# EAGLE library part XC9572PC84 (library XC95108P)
CPLD
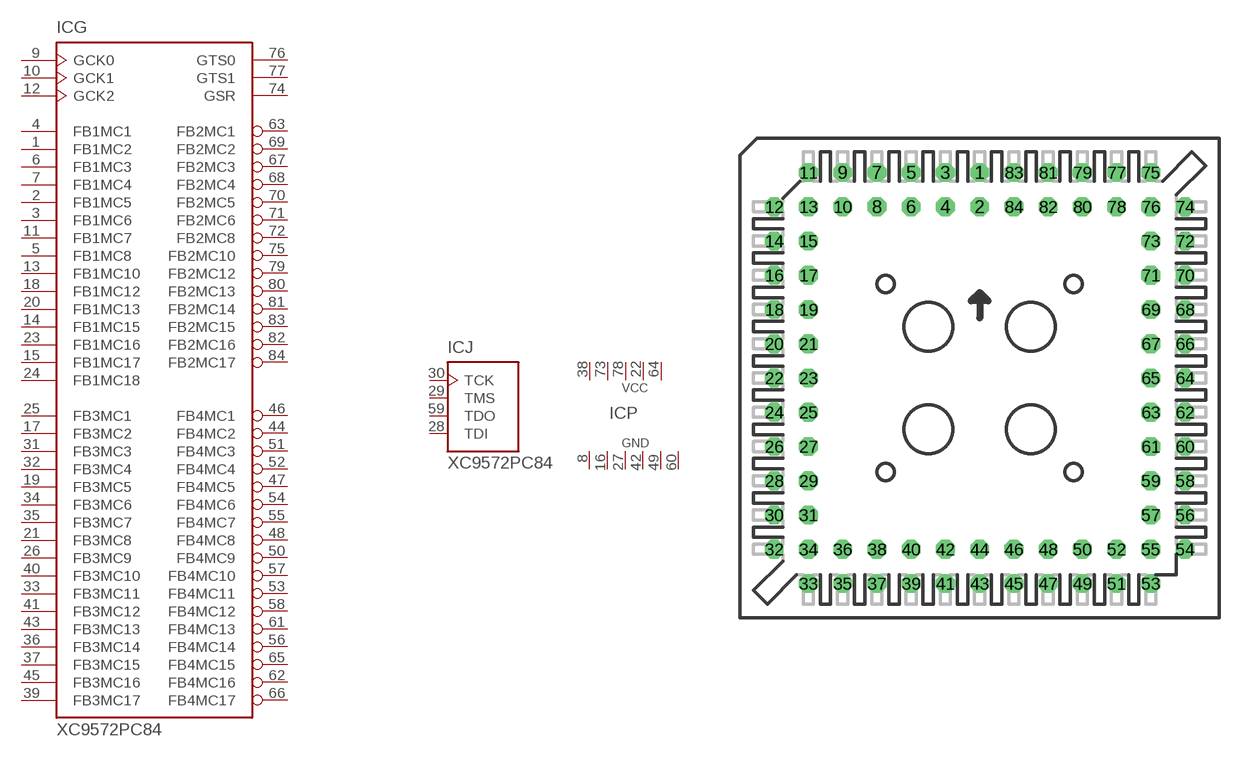
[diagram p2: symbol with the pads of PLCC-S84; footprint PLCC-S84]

Designator prefix IC; gates J=JTAG P=PWR11 G=XC9572

## XC9572PC84  [PLCC-S84]
1  G:FB1MC2
2  G:FB1MC5
3  G:FB1MC6
4  G:FB1MC1
5  G:FB1MC8
6  G:FB1MC3
7  G:FB1MC4
8  P:GND  pwr
9  G:GCK0  in
10  G:GCK1  in
11  G:FB1MC7
12  G:GCK2  in
13  G:FB1MC10
14  G:FB1MC15
15  G:FB1MC17
16  P:GND  pwr
17  G:FB3MC2
18  G:FB1MC12
19  G:FB3MC5
20  G:FB1MC13
21  G:FB3MC8
22  P:VCC  pwr
23  G:FB1MC16
24  G:FB1MC18
25  G:FB3MC1
26  G:FB3MC9
27  P:GND  pwr
28  J:TDI  in
29  J:TMS  in
30  J:TCK  in
31  G:FB3MC3
32  G:FB3MC4
33  G:FB3MC11
34  G:FB3MC6
35  G:FB3MC7
36  G:FB3MC14
37  G:FB3MC15
38  P:VCC  pwr
39  G:FB3MC17
40  G:FB3MC10
41  G:FB3MC12
42  P:GND  pwr
43  G:FB3MC13
44  G:FB4MC2
45  G:FB3MC16
46  G:FB4MC1
47  G:FB4MC5
48  G:FB4MC8
49  P:GND  pwr
50  G:FB4MC9
51  G:FB4MC3
52  G:FB4MC4
53  G:FB4MC11
54  G:FB4MC6
55  G:FB4MC7
56  G:FB4MC14
57  G:FB4MC10
58  G:FB4MC12
59  J:TDO  out
60  P:GND  pwr
61  G:FB4MC13
62  G:FB4MC16
63  G:FB2MC1
64  P:VCC  pwr
65  G:FB4MC15
66  G:FB4MC17
67  G:FB2MC3
68  G:FB2MC4
69  G:FB2MC2
70  G:FB2MC5
71  G:FB2MC6
72  G:FB2MC8
73  P:VCC  pwr
74  G:GSR  in
75  G:FB2MC10
76  G:GTS0  in
77  G:GTS1  in
78  P:VCC  pwr
79  G:FB2MC12
80  G:FB2MC13
81  G:FB2MC14
82  G:FB2MC16
83  G:FB2MC15
84  G:FB2MC17

## Footprint PLCC-S84 (pad centres in mm)
drill 0.889 pad 1.397 octagon: 1 0,15.24; 2 0,12.7; 3 -2.54,15.24; 4 -2.54,12.7; 5 -5.08,15.24; 6 -5.08,12.7; 7 -7.62,15.24; 8 -7.62,12.7; 9 -10.16,15.24; 10 -10.16,12.7; 11 -12.7,15.24; 12 -15.24,12.7; 13 -12.7,12.7; 14 -15.24,10.16; 15 -12.7,10.16; 16 -15.24,7.62; 17 -12.7,7.62; 18 -15.24,5.08; 19 -12.7,5.08; 20 -15.24,2.54; 21 -12.7,2.54; 22 -15.24,0; 23 -12.7,0; 24 -15.24,-2.54; 25 -12.7,-2.54; 26 -15.24,-5.08; 27 -12.7,-5.08; 28 -15.24,-7.62; 29 -12.7,-7.62; 30 -15.24,-10.16; 31 -12.7,-10.16; 32 -15.24,-12.7; 33 -12.7,-15.24; 34 -12.7,-12.7; 35 -10.16,-15.24; 36 -10.16,-12.7; 37 -7.62,-15.24; 38 -7.62,-12.7; 39 -5.08,-15.24; 40 -5.08,-12.7; 41 -2.54,-15.24; 42 -2.54,-12.7; 43 0,-15.24; 44 0,-12.7; 45 2.54,-15.24; 46 2.54,-12.7; 47 5.08,-15.24; 48 5.08,-12.7; 49 7.62,-15.24; 50 7.62,-12.7; 51 10.16,-15.24; 52 10.16,-12.7; 53 12.7,-15.24; 54 15.24,-12.7; 55 12.7,-12.7; 56 15.24,-10.16; 57 12.7,-10.16; 58 15.24,-7.62; 59 12.7,-7.62; 60 15.24,-5.08; 61 12.7,-5.08; 62 15.24,-2.54; 63 12.7,-2.54; 64 15.24,0; 65 12.7,0; 66 15.24,2.54; 67 12.7,2.54; 68 15.24,5.08; 69 12.7,5.08; 70 15.24,7.62; 71 12.7,7.62; 72 15.24,10.16; 73 12.7,10.16; 74 15.24,12.7; 75 12.7,15.24; 76 12.7,12.7; 77 10.16,15.24; 78 10.16,12.7; 79 7.62,15.24; 80 7.62,12.7; 81 5.08,15.24; 82 5.08,12.7; 83 2.54,15.24; 84 2.54,12.7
